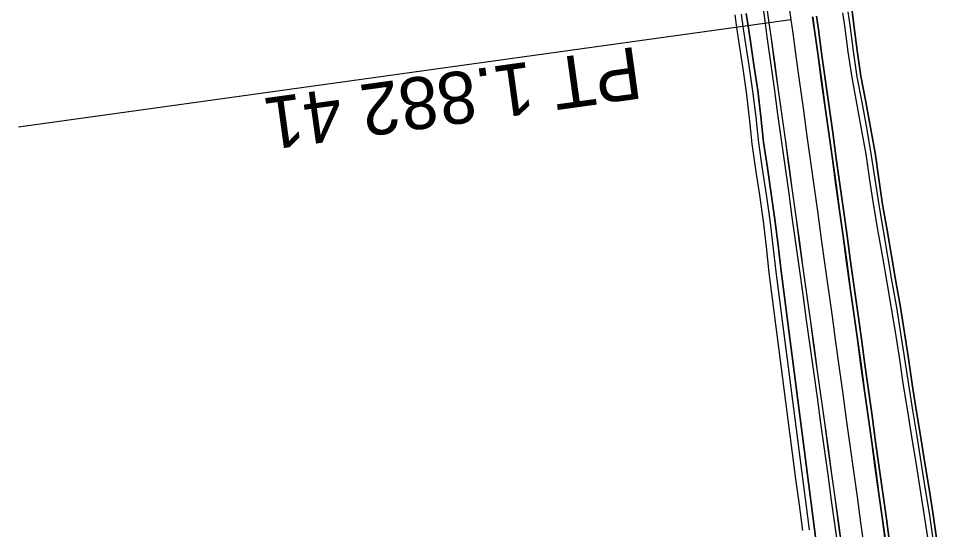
# Model space of a CAD drawing. Extents: x -646586 to -642452, y -1121394 to -1115665.
# Drawn here: x -643856.7 to -643680, y -1118753.8 to -1118655.5 of the extents above; entities that cross this region are included whole.
import ezdxf

# ---------------------------------------------------------------- set-up
doc = ezdxf.new("R2010")
doc.units = 0
for name, color, linetype in [('Nevyplněná území', 7, 'Continuous'), ('Parcela projektu', 7, 'Continuous'), ('PLOCHY', 7, 'Continuous'), ('Situace_dno_prikopu', 7, 'Continuous'), ('Situace_hrany', 7, 'Continuous'), ('Situace_osy', 7, 'Continuous'), ('Situace_pata_nasypu', 7, 'Continuous'), ('Situace_pata_zarezu', 7, 'Continuous')]:
    doc.layers.add(name, color=color, linetype=linetype)

msp = doc.modelspace()

# ---------------------------------------------------------------- linework, layer by layer
at = {"layer": 'Nevyplněná území'}
for points in [[(-643712.62, -1118654.01), (-643712.29, -1118656.4), (-643711.94, -1118658.96), (-643711.25, -1118663.91), (-643710.56, -1118668.86), (-643709.87, -1118673.82), (-643709.19, -1118678.77), (-643708.5, -1118683.72), (-643707.81, -1118688.67), (-643707.12, -1118693.63), (-643706.44, -1118698.58), (-643705.75, -1118703.53), (-643705.06, -1118708.48), (-643704.37, -1118713.44), (-643703.68, -1118718.39), (-643703, -1118723.34), (-643702.31, -1118728.29), (-643701.62, -1118733.25), (-643700.93, -1118738.2), (-643700.25, -1118743.15), (-643699.56, -1118748.1), (-643698.87, -1118753.06), (-643698.18, -1118758.01)], [(-643703.87, -1118655.23), (-643703.52, -1118657.79), (-643702.83, -1118662.74), (-643702.14, -1118667.7), (-643701.45, -1118672.65), (-643700.77, -1118677.6), (-643700.08, -1118682.55), (-643699.39, -1118687.51), (-643698.7, -1118692.46), (-643698.02, -1118697.41), (-643697.33, -1118702.36), (-643696.64, -1118707.32), (-643695.95, -1118712.27), (-643695.26, -1118717.22), (-643694.58, -1118722.17), (-643693.89, -1118727.13), (-643693.2, -1118732.08), (-643692.51, -1118737.03), (-643691.83, -1118741.98), (-643691.14, -1118746.94), (-643690.45, -1118751.89), (-643689.76, -1118756.84)]]:
    msp.add_lwpolyline(points, dxfattribs=at)
at = {"layer": 'Parcela projektu'}
msp.add_lwpolyline([(-643708.08, -1118655.81), (-643856.66, -1118676.44)], dxfattribs=at)
msp.add_lwpolyline([(-643708.08, -1118655.81), (-643856.66, -1118676.44)], dxfattribs=at)
at = {"layer": 'PLOCHY'}
for p, q in [((-643712.64, -1118654.02), (-643712.31, -1118656.41)), ((-643712.31, -1118656.41), (-643711.96, -1118658.97)), ((-643703.54, -1118657.8), (-643703.89, -1118655.24)), ((-643702.85, -1118662.75), (-643703.54, -1118657.8)), ((-643711.96, -1118658.97), (-643711.27, -1118663.92)), ((-643702.16, -1118667.71), (-643702.85, -1118662.75)), ((-643711.27, -1118663.92), (-643710.58, -1118668.88)), ((-643701.47, -1118672.66), (-643702.16, -1118667.71)), ((-643710.58, -1118668.88), (-643709.89, -1118673.83)), ((-643709.89, -1118673.83), (-643709.2, -1118678.78)), ((-643700.79, -1118677.61), (-643701.47, -1118672.66)), ((-643700.1, -1118682.56), (-643700.79, -1118677.61)), ((-643709.2, -1118678.78), (-643708.52, -1118683.73)), ((-643699.41, -1118687.52), (-643700.1, -1118682.56)), ((-643708.52, -1118683.73), (-643707.83, -1118688.69)), ((-643698.72, -1118692.47), (-643699.41, -1118687.52)), ((-643707.83, -1118688.69), (-643707.14, -1118693.64)), ((-643698.03, -1118697.42), (-643698.72, -1118692.47)), ((-643707.14, -1118693.64), (-643706.45, -1118698.59)), ((-643706.45, -1118698.59), (-643705.77, -1118703.54)), ((-643697.35, -1118702.37), (-643698.03, -1118697.42)), ((-643696.66, -1118707.33), (-643697.35, -1118702.37)), ((-643705.77, -1118703.54), (-643705.08, -1118708.5)), ((-643695.97, -1118712.28), (-643696.66, -1118707.33)), ((-643705.08, -1118708.5), (-643704.39, -1118713.45)), ((-643695.28, -1118717.23), (-643695.97, -1118712.28)), ((-643704.39, -1118713.45), (-643703.7, -1118718.4)), ((-643694.6, -1118722.18), (-643695.28, -1118717.23)), ((-643703.7, -1118718.4), (-643703.01, -1118723.35)), ((-643703.01, -1118723.35), (-643702.33, -1118728.31)), ((-643693.91, -1118727.14), (-643694.6, -1118722.18)), ((-643693.22, -1118732.09), (-643693.91, -1118727.14)), ((-643702.33, -1118728.31), (-643701.64, -1118733.26)), ((-643692.53, -1118737.04), (-643693.22, -1118732.09)), ((-643701.64, -1118733.26), (-643700.95, -1118738.21)), ((-643691.84, -1118741.99), (-643692.53, -1118737.04)), ((-643700.95, -1118738.21), (-643700.26, -1118743.16)), ((-643691.16, -1118746.95), (-643691.84, -1118741.99)), ((-643700.26, -1118743.16), (-643699.58, -1118748.12)), ((-643699.58, -1118748.12), (-643698.89, -1118753.07)), ((-643690.47, -1118751.9), (-643691.16, -1118746.95)), ((-643698.89, -1118753.07), (-643698.2, -1118758.02)), ((-643689.78, -1118756.85), (-643690.47, -1118751.9))]:
    msp.add_line(p, q, dxfattribs=at)
for points in [[(-643702.91, -1118758.67), (-643703.55, -1118753.71), (-643704.19, -1118748.75), (-643704.83, -1118743.79), (-643705.48, -1118738.83), (-643706.12, -1118733.87), (-643706.76, -1118728.91), (-643707.4, -1118723.95), (-643708.04, -1118719), (-643708.69, -1118714.04), (-643709.33, -1118709.08), (-643709.97, -1118704.12), (-643710.54, -1118699.15), (-643711.15, -1118694.19), (-643711.87, -1118689.24), (-643712.6, -1118684.29), (-643713.31, -1118679.34), (-643713.84, -1118674.37), (-643714.45, -1118669.41), (-643715.19, -1118664.46), (-643715.93, -1118659.51), (-643716.31, -1118656.96), (-643716.67, -1118654.57)], [(-643702.91, -1118758.67), (-643703.55, -1118753.71), (-643704.19, -1118748.75), (-643704.83, -1118743.79), (-643705.48, -1118738.83), (-643706.12, -1118733.87), (-643706.76, -1118728.91), (-643707.4, -1118723.95), (-643708.04, -1118718.99), (-643708.69, -1118714.03), (-643709.33, -1118709.08), (-643709.97, -1118704.12), (-643710.54, -1118699.15), (-643711.15, -1118694.19), (-643711.87, -1118689.24), (-643712.6, -1118684.29), (-643713.31, -1118679.34), (-643713.84, -1118674.37), (-643714.45, -1118669.4), (-643715.19, -1118664.46), (-643715.93, -1118659.51), (-643716.31, -1118656.95), (-643716.67, -1118654.57)], [(-643713.37, -1118654.11), (-643713.03, -1118656.5), (-643712.68, -1118659.06), (-643711.99, -1118664.01), (-643711.3, -1118668.97), (-643710.62, -1118673.92), (-643709.93, -1118678.87), (-643709.24, -1118683.82), (-643708.55, -1118688.78), (-643707.86, -1118693.73), (-643707.18, -1118698.68), (-643706.49, -1118703.63), (-643705.8, -1118708.59), (-643705.11, -1118713.54), (-643704.43, -1118718.49), (-643703.74, -1118723.44), (-643703.05, -1118728.4), (-643702.36, -1118733.35), (-643701.68, -1118738.3), (-643700.99, -1118743.25), (-643700.3, -1118748.21), (-643699.61, -1118753.16), (-643698.92, -1118758.11)], [(-643698.12, -1118654.43), (-643697.74, -1118656.99), (-643697.12, -1118661.95), (-643696.37, -1118666.89), (-643695.44, -1118671.81), (-643694.55, -1118676.74), (-643693.66, -1118681.66), (-643692.94, -1118686.61), (-643692.18, -1118691.55), (-643691.32, -1118696.48), (-643690.47, -1118701.41), (-643689.62, -1118706.34), (-643688.76, -1118711.27), (-643687.95, -1118716.2), (-643687.2, -1118721.15), (-643686.45, -1118726.09), (-643685.66, -1118731.03), (-643684.86, -1118735.97), (-643684.07, -1118740.91), (-643683.27, -1118745.84), (-643682.48, -1118750.78), (-643681.76, -1118755.73)], [(-643698.12, -1118654.43), (-643697.74, -1118656.99), (-643697.11, -1118661.95), (-643696.37, -1118666.89), (-643695.43, -1118671.81), (-643694.55, -1118676.74), (-643693.66, -1118681.66), (-643692.94, -1118686.61), (-643692.18, -1118691.55), (-643691.32, -1118696.48), (-643690.47, -1118701.41), (-643689.62, -1118706.34), (-643688.76, -1118711.27), (-643687.95, -1118716.2), (-643687.2, -1118721.15), (-643686.45, -1118726.09), (-643685.66, -1118731.03), (-643684.86, -1118735.97), (-643684.07, -1118740.9), (-643683.27, -1118745.84), (-643682.48, -1118750.78), (-643681.76, -1118755.73)], [(-643680.04, -1118755.49), (-643680.76, -1118750.54), (-643681.56, -1118745.61), (-643682.36, -1118740.67), (-643683.15, -1118735.73), (-643683.95, -1118730.79), (-643684.74, -1118725.85), (-643685.47, -1118720.91), (-643686.22, -1118715.97), (-643687.02, -1118711.03), (-643687.87, -1118706.1), (-643688.72, -1118701.17), (-643689.58, -1118696.24), (-643690.43, -1118691.31), (-643691.18, -1118686.37), (-643691.88, -1118681.41), (-643692.76, -1118676.49), (-643693.65, -1118671.56), (-643694.59, -1118666.65), (-643695.31, -1118661.7), (-643695.94, -1118656.74), (-643696.28, -1118654.17)], [(-643718.86, -1118654.87), (-643718.51, -1118657.26), (-643718.13, -1118659.82), (-643717.39, -1118664.77), (-643716.65, -1118669.71), (-643716.07, -1118674.68), (-643715.57, -1118679.66), (-643714.86, -1118684.61), (-643714.14, -1118689.55), (-643713.42, -1118694.5), (-643712.83, -1118699.47), (-643712.29, -1118704.44), (-643711.65, -1118709.4), (-643711.01, -1118714.36), (-643710.37, -1118719.32), (-643709.72, -1118724.28), (-643709.08, -1118729.24), (-643708.44, -1118734.19), (-643707.8, -1118739.15), (-643707.16, -1118744.11), (-643706.51, -1118749.07), (-643705.87, -1118754.03)], [(-643689.02, -1118756.74), (-643689.71, -1118751.78), (-643690.39, -1118746.83), (-643691.08, -1118741.88), (-643691.77, -1118736.93), (-643692.46, -1118731.97), (-643693.15, -1118727.02), (-643693.83, -1118722.07), (-643694.52, -1118717.12), (-643695.21, -1118712.16), (-643695.9, -1118707.21), (-643696.58, -1118702.26), (-643697.27, -1118697.31), (-643697.96, -1118692.35), (-643698.65, -1118687.4), (-643699.34, -1118682.45), (-643700.02, -1118677.5), (-643700.71, -1118672.54), (-643701.4, -1118667.59), (-643702.09, -1118662.64), (-643702.77, -1118657.69), (-643703.13, -1118655.12)]]:
    msp.add_lwpolyline(points, dxfattribs=at)
at = {"layer": 'Situace_dno_prikopu'}
for points in [[(-643717.66, -1118654.71), (-643717.3, -1118657.09), (-643716.92, -1118659.65), (-643716.18, -1118664.6), (-643715.44, -1118669.54), (-643714.83, -1118674.51), (-643714.3, -1118679.48), (-643713.59, -1118684.43), (-643712.86, -1118689.38), (-643712.14, -1118694.32), (-643711.53, -1118699.29), (-643710.96, -1118704.26), (-643710.32, -1118709.21), (-643709.68, -1118714.17), (-643709.03, -1118719.13), (-643708.39, -1118724.09), (-643707.75, -1118729.05), (-643707.11, -1118734.01), (-643706.47, -1118738.97), (-643705.83, -1118743.93), (-643705.18, -1118748.89), (-643704.54, -1118753.84)], [(-643697.13, -1118654.29), (-643696.75, -1118656.85), (-643696.12, -1118661.81), (-643695.38, -1118666.76), (-643694.44, -1118671.67), (-643693.56, -1118676.6), (-643692.67, -1118681.52), (-643691.95, -1118686.47), (-643691.19, -1118691.41), (-643690.33, -1118696.34), (-643689.48, -1118701.27), (-643688.63, -1118706.2), (-643687.77, -1118711.13), (-643686.96, -1118716.07), (-643686.21, -1118721.01), (-643685.46, -1118725.95), (-643684.67, -1118730.89), (-643683.87, -1118735.83), (-643683.08, -1118740.77), (-643682.28, -1118745.7), (-643681.49, -1118750.64), (-643680.77, -1118755.59)]]:
    msp.add_lwpolyline(points, dxfattribs=at)
at = {"layer": 'Situace_hrany'}
for points in [[(-643713.37, -1118654.11), (-643713.04, -1118656.5), (-643712.68, -1118659.06), (-643711.99, -1118664.02), (-643711.3, -1118668.97), (-643710.62, -1118673.92), (-643709.93, -1118678.87), (-643709.24, -1118683.83), (-643708.55, -1118688.78), (-643707.87, -1118693.73), (-643707.18, -1118698.68), (-643706.49, -1118703.64), (-643705.8, -1118708.59), (-643705.11, -1118713.54), (-643704.43, -1118718.49), (-643703.74, -1118723.45), (-643703.05, -1118728.4), (-643702.36, -1118733.35), (-643701.68, -1118738.3), (-643700.99, -1118743.26), (-643700.3, -1118748.21), (-643699.61, -1118753.16), (-643698.93, -1118758.11)], [(-643703.13, -1118655.12), (-643702.78, -1118657.69), (-643702.09, -1118662.64), (-643701.4, -1118667.59), (-643700.71, -1118672.54), (-643700.02, -1118677.5), (-643699.34, -1118682.45), (-643698.65, -1118687.4), (-643697.96, -1118692.35), (-643697.27, -1118697.31), (-643696.59, -1118702.26), (-643695.9, -1118707.21), (-643695.21, -1118712.16), (-643694.52, -1118717.12), (-643693.83, -1118722.07), (-643693.15, -1118727.02), (-643692.46, -1118731.97), (-643691.77, -1118736.93), (-643691.08, -1118741.88), (-643690.4, -1118746.83), (-643689.71, -1118751.78), (-643689.02, -1118756.74)]]:
    msp.add_lwpolyline(points, dxfattribs=at)
at = {"layer": 'Situace_osy'}
msp.add_lwpolyline([(-643708.42, -1118653.42), (-643708.08, -1118655.81), (-643707.73, -1118658.38), (-643707.04, -1118663.33), (-643706.35, -1118668.28), (-643705.66, -1118673.23), (-643704.98, -1118678.19), (-643704.29, -1118683.14), (-643703.6, -1118688.09), (-643702.91, -1118693.04), (-643702.23, -1118697.99), (-643701.54, -1118702.95), (-643700.85, -1118707.9), (-643700.16, -1118712.85), (-643699.47, -1118717.8), (-643698.79, -1118722.76), (-643698.1, -1118727.71), (-643697.41, -1118732.66), (-643696.72, -1118737.61), (-643696.04, -1118742.57), (-643695.35, -1118747.52), (-643694.66, -1118752.47), (-643693.97, -1118757.42)], dxfattribs=at)
at = {"layer": 'Situace_pata_nasypu'}
for points in [[(-643716.67, -1118654.57), (-643716.31, -1118656.95), (-643715.93, -1118659.51), (-643715.19, -1118664.46), (-643714.45, -1118669.41), (-643713.84, -1118674.37), (-643713.31, -1118679.34), (-643712.6, -1118684.29), (-643711.87, -1118689.24), (-643711.15, -1118694.19), (-643710.54, -1118699.15), (-643709.97, -1118704.12), (-643709.33, -1118709.08), (-643708.69, -1118714.04), (-643708.04, -1118718.99), (-643707.4, -1118723.95), (-643706.76, -1118728.91), (-643706.12, -1118733.87), (-643705.48, -1118738.83), (-643704.83, -1118743.79), (-643704.19, -1118748.75), (-643703.55, -1118753.71), (-643702.91, -1118758.67)], [(-643698.12, -1118654.43), (-643697.74, -1118656.99), (-643697.12, -1118661.95), (-643696.37, -1118666.89), (-643695.44, -1118671.81), (-643694.55, -1118676.74), (-643693.66, -1118681.66), (-643692.94, -1118686.61), (-643692.18, -1118691.55), (-643691.32, -1118696.48), (-643690.47, -1118701.41), (-643689.62, -1118706.34), (-643688.76, -1118711.27), (-643687.95, -1118716.2), (-643687.2, -1118721.15), (-643686.45, -1118726.09), (-643685.66, -1118731.03), (-643684.86, -1118735.97), (-643684.07, -1118740.91), (-643683.27, -1118745.84), (-643682.48, -1118750.78), (-643681.76, -1118755.73)]]:
    msp.add_lwpolyline(points, dxfattribs=at)
at = {"layer": 'Situace_pata_zarezu'}
for points in [[(-643696.28, -1118654.17), (-643695.94, -1118656.74), (-643695.31, -1118661.7), (-643694.59, -1118666.65), (-643693.65, -1118671.56), (-643692.76, -1118676.49), (-643691.88, -1118681.41), (-643691.18, -1118686.37), (-643690.43, -1118691.31), (-643689.58, -1118696.24), (-643688.72, -1118701.17), (-643687.87, -1118706.1), (-643687.02, -1118711.03), (-643686.22, -1118715.96), (-643685.47, -1118720.91), (-643684.74, -1118725.85), (-643683.95, -1118730.79), (-643683.15, -1118735.73), (-643682.36, -1118740.67), (-643681.56, -1118745.6), (-643680.76, -1118750.54), (-643680.04, -1118755.49)], [(-643718.86, -1118654.87), (-643718.51, -1118657.26), (-643718.13, -1118659.82), (-643717.39, -1118664.76), (-643716.65, -1118669.71), (-643716.07, -1118674.68), (-643715.57, -1118679.66), (-643714.86, -1118684.61), (-643714.14, -1118689.55), (-643713.42, -1118694.5), (-643712.83, -1118699.47), (-643712.29, -1118704.44), (-643711.65, -1118709.4), (-643711.01, -1118714.36), (-643710.37, -1118719.32), (-643709.72, -1118724.28), (-643709.08, -1118729.24), (-643708.44, -1118734.19), (-643707.8, -1118739.15), (-643707.16, -1118744.11), (-643706.51, -1118749.07), (-643705.87, -1118754.03)]]:
    msp.add_lwpolyline(points, dxfattribs=at)

# ---------------------------------------------------------------- texts
at = {"layer": 'Parcela projektu'}
msp.add_text('PT 1.882 41', height=10, rotation=187.9061, dxfattribs=at).set_placement((-643737.66, -1118660.93))
msp.add_text('PT 1.882 41', height=10, rotation=187.9061, dxfattribs=at).set_placement((-643737.66, -1118660.93))

doc.saveas('drawing.dxf')
